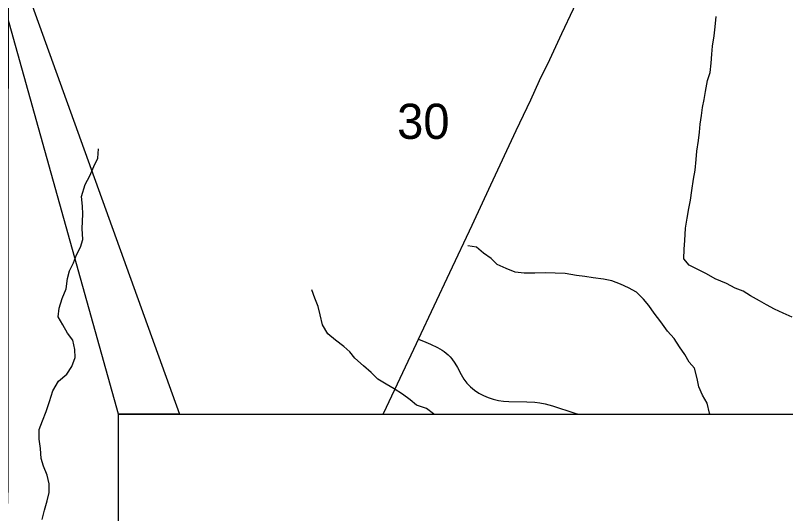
# Model space of a CAD drawing. Extents: x 0 to 34, y 0 to 22.
# Drawn here: x 5.655 to 6.57, y 16.861 to 17.454 of the extents above; entities that cross this region are included whole.
import ezdxf

# ---------------------------------------------------------------- set-up
doc = ezdxf.new("R2010")
doc.units = 0
for name, color, linetype in [('Default', 7, 'Continuous'), ('GM_X_Minor_River', 7, 'Continuous'), ('GM_X_Section', 7, 'Continuous'), ('GM_X_Section_Text', 7, 'Continuous'), ('GM_X_State_Route', 7, 'Continuous'), ('GM_X_Township_Road', 7, 'Continuous'), ('SH_Text', 7, 'Continuous')]:
    doc.layers.add(name, color=color, linetype=linetype)

msp = doc.modelspace()

# ---------------------------------------------------------------- linework, layer by layer
at = {"layer": 'Default'}
msp.add_lwpolyline([(5.77739, 16.97974), (5.52747, 17.87382), (5.84994, 16.97974)], close=True, dxfattribs=at)
at = {"layer": 'GM_X_Minor_River'}
for points in [[(6.57768, 17.09492), (6.56712, 17.0999), (6.55692, 17.1045), (6.54711, 17.10986), (6.53881, 17.11446), (6.52824, 17.12058), (6.51957, 17.12593), (6.51013, 17.12939), (6.49957, 17.13514), (6.48635, 17.14051), (6.47616, 17.14663), (6.46559, 17.15162), (6.45541, 17.15698), (6.44901, 17.16422), (6.44943, 17.17598), (6.45022, 17.18622), (6.45103, 17.20102), (6.45297, 17.21277), (6.45491, 17.22414), (6.45683, 17.234), (6.45877, 17.24575), (6.46071, 17.25902), (6.46264, 17.26964), (6.46383, 17.28253), (6.46462, 17.29239), (6.46656, 17.30491), (6.46773, 17.31515), (6.46853, 17.32463), (6.47008, 17.33487), (6.47125, 17.34435), (6.47317, 17.35382), (6.47472, 17.3633), (6.47704, 17.37657), (6.48048, 17.38604), (6.48166, 17.39704), (6.48246, 17.40766), (6.48325, 17.41714), (6.48519, 17.42965), (6.48636, 17.44027), (6.48754, 17.45241)], [(5.68663, 16.8545), (5.6897, 16.86549), (5.69277, 16.87648), (5.69507, 16.88634), (5.69511, 16.89696), (5.69289, 16.90722), (5.68839, 16.91786), (5.6854, 16.92698), (5.68469, 16.93875), (5.68322, 16.94976), (5.68326, 16.96152), (5.68708, 16.97175), (5.69166, 16.98273), (5.69549, 16.99486), (5.69932, 17.00736), (5.70617, 17.01871), (5.71603, 17.02739), (5.72212, 17.03646), (5.72594, 17.04707), (5.7256, 17.05656), (5.72299, 17.06757), (5.71697, 17.07595), (5.71134, 17.08584), (5.7057, 17.09536), (5.70688, 17.1056), (5.7107, 17.11734), (5.71528, 17.1287), (5.71684, 17.14084), (5.71915, 17.15031), (5.7241, 17.15977), (5.72754, 17.16924), (5.73211, 17.17833), (5.73517, 17.18742), (5.73409, 17.20032), (5.73491, 17.2174), (5.73457, 17.22688), (5.73348, 17.23865), (5.73769, 17.25267), (5.7434, 17.26289), (5.74798, 17.27425), (5.75293, 17.28409), (5.75373, 17.29509)], [(6.47977, 16.97974), (6.47969, 16.9808), (6.47671, 16.99258), (6.47145, 17.00209), (6.46695, 17.01236), (6.46472, 17.02223), (6.46174, 17.03439), (6.45534, 17.04163), (6.45046, 17.05076), (6.44407, 17.0599), (6.43768, 17.06979), (6.42977, 17.07856), (6.42187, 17.0896), (6.41397, 17.09989), (6.40758, 17.10902), (6.40117, 17.11626), (6.39289, 17.12465), (6.38346, 17.13001), (6.37402, 17.13423), (6.36345, 17.13807), (6.35362, 17.14002), (6.34153, 17.1416), (6.33132, 17.14354), (6.3215, 17.14473), (6.30827, 17.14707), (6.29617, 17.14751), (6.28483, 17.14756), (6.27197, 17.14725), (6.25949, 17.14731), (6.24853, 17.1485), (6.23796, 17.15272), (6.22739, 17.15771), (6.22023, 17.16495), (6.21118, 17.17107), (6.20289, 17.17832), (6.19231, 17.17989)], [(6.15228, 16.97974), (6.15184, 16.98012), (6.14317, 16.98623), (6.13146, 16.99046), (6.12392, 16.99657), (6.11487, 17.00344), (6.10507, 17.00994), (6.09563, 17.0153), (6.08545, 17.02142), (6.07754, 17.02905), (6.06849, 17.03706), (6.05832, 17.04621), (6.0523, 17.05383), (6.04514, 17.06032), (6.03533, 17.06757), (6.02628, 17.07521), (6.0199, 17.08586), (6.01692, 17.09764), (6.01469, 17.10752), (6.01057, 17.11778), (6.0072, 17.12766)]]:
    msp.add_lwpolyline(points, dxfattribs=at)
at = {"layer": 'GM_X_Section'}
msp.add_lwpolyline([(6.80358, 16.97974), (6.79787, 17.8558), (5.64653, 17.84104), (5.64591, 16.89266), (5.64405, 16.82785), (5.77739, 16.82938), (5.77739, 16.97974)], close=True, dxfattribs=at)
at = {"layer": 'GM_X_State_Route'}
for points in [[(6.09203, 16.97974), (6.09588, 16.98793), (6.13156, 17.06372), (6.134, 17.06894), (6.17102, 17.14822), (6.19747, 17.20447), (6.21966, 17.25243), (6.25008, 17.31714), (6.2675, 17.35359), (6.27776, 17.37626), (6.28978, 17.4015), (6.30419, 17.43251), (6.33198, 17.49156), (6.35146, 17.53392), (6.38213, 17.59896)], [(5.77739, 16.26262), (5.77739, 16.97974), (7.8038, 16.97974)]]:
    msp.add_lwpolyline(points, dxfattribs=at)
at = {"layer": 'GM_X_Township_Road'}
msp.add_lwpolyline([(6.134, 17.06894), (6.14246, 17.06541), (6.14817, 17.06302), (6.15649, 17.05886), (6.16187, 17.05574), (6.16445, 17.05402), (6.1669, 17.05212), (6.16922, 17.05008), (6.17137, 17.04786), (6.17338, 17.04551), (6.17694, 17.04044), (6.18003, 17.03505), (6.18436, 17.02678), (6.18757, 17.02147), (6.19129, 17.01651), (6.19558, 17.01205), (6.20041, 17.00816), (6.20562, 17.00479), (6.2111, 17.00187), (6.2168, 16.99944), (6.22269, 16.9975), (6.22872, 16.99604), (6.23483, 16.99507), (6.241, 16.99454), (6.26268, 16.9944), (6.27194, 16.99385), (6.27809, 16.99308), (6.28415, 16.99186), (6.29311, 16.98938), (6.31971, 16.98095), (6.32424, 16.97974)], dxfattribs=at)
at = {"layer": 'SH_Text'}
msp.add_lwpolyline([(5.77739, 16.97974), (7.99724, 16.97974), (7.99724, 16.26262), (5.77739, 16.26262)], close=True, dxfattribs=at)

# ---------------------------------------------------------------- texts
at = {"layer": 'GM_X_Section_Text'}
msp.add_text('30', height=0.041856, rotation=0.00001, dxfattribs=at).set_placement((6.10846, 17.307))

doc.saveas('drawing.dxf')
